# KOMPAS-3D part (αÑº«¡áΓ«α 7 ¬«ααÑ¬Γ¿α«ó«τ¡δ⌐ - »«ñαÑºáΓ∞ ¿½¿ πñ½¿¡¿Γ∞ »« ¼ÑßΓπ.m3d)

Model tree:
1. Эскиз:1
2. Операция выдавливания:1
     Толщина стенки 1 = 2; Толщина стенки 2 = 8; Расстояние 1 = 1
3. Эскиз:3
4. Операция выдавливания:2
     Толщина стенки 1 = 2; Толщина стенки 2 = 6; Расстояние 1 = 5.5
5. Эскиз:4
6. Операция выдавливания:3
     Толщина стенки 1 = 2; Толщина стенки 2 = 6; Расстояние 1 = 1
7. Эскиз:5
8. Эскиз:6
9. Операция выдавливания:4
     Толщина стенки 1 = 2; Толщина стенки 2 = 2.5; Расстояние 1 = 50
10. Эскиз:7
11. Вырезать элемент выдавливания:1
     Толщина стенки 2 = 1.5; Расстояние 1 = 40
12. Эскиз:8
13. Операция выдавливания:5
     Толщина стенки 1 = 2; Толщина стенки 2 = 2.5; Расстояние 1 = 50
14. Эскиз:9
15. Вырезать элемент выдавливания:2
     Толщина стенки 2 = 1.5; Расстояние 1 = 40
16. Эскиз:10
17. Операция выдавливания:6
     Толщина стенки 1 = 2; Толщина стенки 2 = 2.5; Расстояние 1 = 10
18. Эскиз:11
19. Операция выдавливания:7
     Толщина стенки 1 = 2; Толщина стенки 2 = 6; Расстояние 1 = 1
20. Эскиз:12
21. Операция выдавливания:8
     Толщина стенки 1 = 2; Толщина стенки 2 = 6; Расстояние 1 = 5.5
22. Эскиз:13
23. Операция выдавливания:9
     Толщина стенки 1 = 2; Толщина стенки 2 = 8; Расстояние 1 = 1
24. Эскиз:14
25. Вырезать элемент выдавливания:3
     Толщина стенки 2 = 1.5; Расстояние 1 = 23
26. Эскиз:15
27. Вырезать элемент выдавливания:4
     Толщина стенки 2 = 1.5; Расстояние 1 = 1
28. Эскиз:16
29. Вырезать элемент выдавливания:5
     Расстояние 1 = 150
30. Эскиз:21
31. Вырезать элемент выдавливания:6
     Расстояние 1 = 20
